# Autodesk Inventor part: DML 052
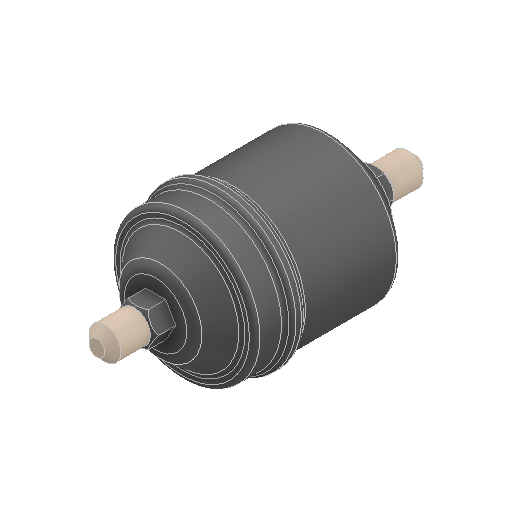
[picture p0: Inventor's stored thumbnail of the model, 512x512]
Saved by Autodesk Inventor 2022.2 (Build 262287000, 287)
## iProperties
Created: 2015-01
Part Number: DML 052
Material: Generico
Document SubType Name: Modeling
Designer: 18907419
Density: 1 g/cm^3
Appearance: Default
Author: 18907419
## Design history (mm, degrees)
feature "Solido1"
node "Solido2"
